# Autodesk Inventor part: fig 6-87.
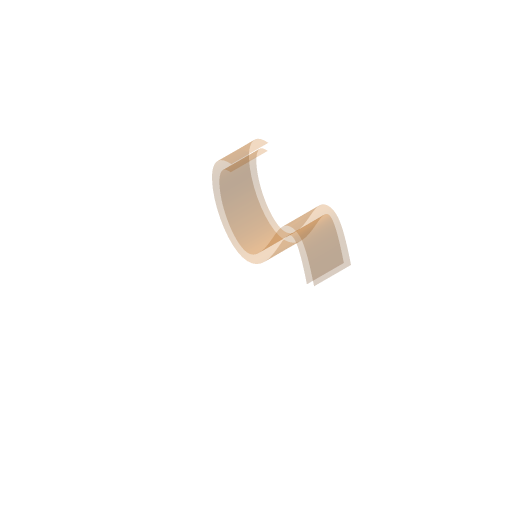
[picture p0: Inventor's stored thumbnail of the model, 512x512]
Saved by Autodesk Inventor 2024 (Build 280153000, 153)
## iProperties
Shininess: 64.0
Length Units: 11269
Angle Units: 11279
Time Units: 11290
Mass Units: 11283
Length Display Precision: 3
Angle Display Precision: 2
Compacted: True
Part Number: fig 6-87.
Document SubType Name: Modeling
Created: 2002-12
Designer: deepak
Density: 1 g/cm^3
Material: Generic
Appearance: Default
Density: 0.0
Volumn: 0.0
Area: 0.0
PropertySet Name: Model Information
Control State: 0
Master: False
Checked Out: False
Author: deepak
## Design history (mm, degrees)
sketch "Sketch1"
  geometry: 5 further points
  constraints: 5 other
extrude_surface "ExtrusionSrf1" sketch "Sketch1" dims "d0" = 20, "d1" = 0
feature "OffsetSrf2" dims "d8" = 4, "d9" = 4
body "Solid1"
body "Srf1"
body "Srf2"
